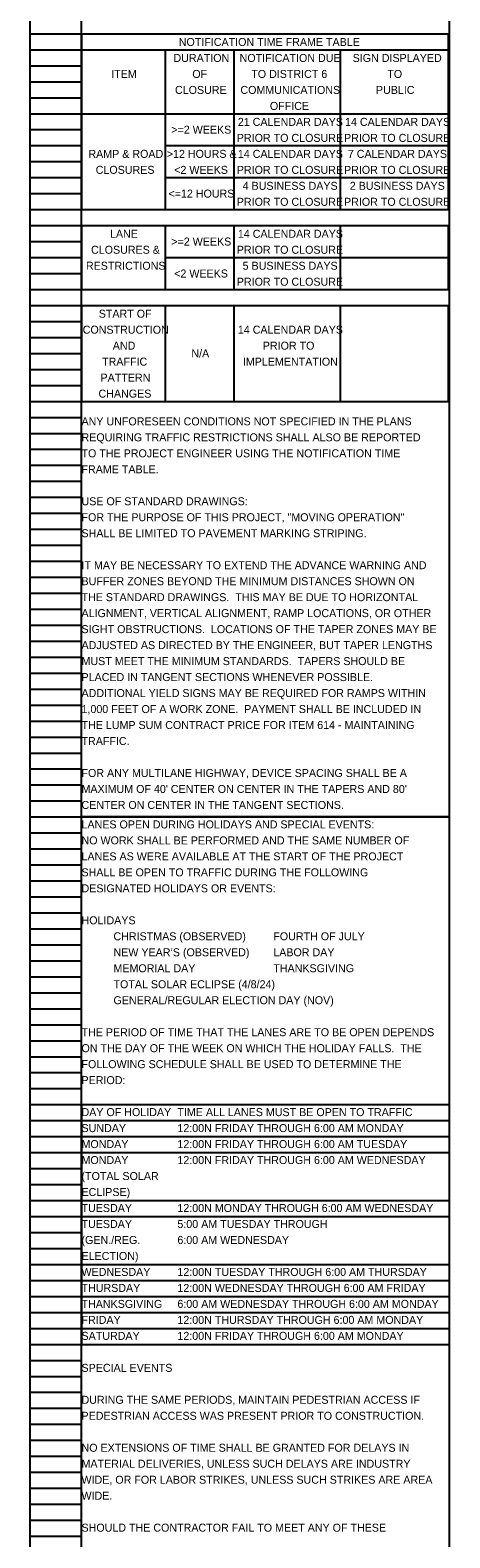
# Model space of a CAD drawing. Extents: x 16463 to 16500, y 5400 to 5823.
# Drawn here: x 16463.05 to 16470.4, y 5770.52 to 5796.94 of the extents above; entities that cross this region are included whole.
import ezdxf

# ---------------------------------------------------------------- set-up
doc = ezdxf.new("R2010")
doc.units = 0
for name, color, linetype in [('Default', 7, 'Continuous'), ('SC_Scratch1', 7, 'Continuous'), ('SH_Data', 7, 'Continuous')]:
    doc.layers.add(name, color=color, linetype=linetype)

msp = doc.modelspace()

# ---------------------------------------------------------------- linework, layer by layer
at = {"layer": 'Default'}
for p, q in [((16463.949, 5778.112), (16470.389, 5778.112)), ((16463.949, 5777.832), (16470.389, 5777.832)), ((16463.949, 5777.552), (16470.389, 5777.552)), ((16463.949, 5777.272), (16470.389, 5777.272)), ((16463.949, 5776.432), (16470.389, 5776.432)), ((16463.949, 5776.152), (16470.389, 5776.152)), ((16463.949, 5775.312), (16470.389, 5775.312)), ((16463.949, 5775.032), (16470.389, 5775.032)), ((16463.949, 5774.752), (16470.389, 5774.752)), ((16463.949, 5774.472), (16470.389, 5774.472)), ((16463.949, 5774.192), (16470.389, 5774.192))]:
    msp.add_line(p, q, dxfattribs=at)
for points in [[(16463.949, 5778.112), (16463.949, 5773.912), (16470.389, 5773.912)], [(16463.949, 5778.112), (16470.389, 5778.112), (16470.389, 5773.912)]]:
    msp.add_lwpolyline(points, dxfattribs=at)
at = {"layer": 'SC_Scratch1'}
for points in [[(16463.949, 5803.312), (16470.389, 5803.312), (16470.389, 5783.152), (16463.949, 5783.152)], [(16463.949, 5783.152), (16470.389, 5783.152), (16470.389, 5762.992), (16463.949, 5762.992)]]:
    msp.add_lwpolyline(points, close=True, dxfattribs=at)
at = {"layer": 'SH_Data'}
for p, q in [((16463.049, 5783.152), (16463.049, 5803.312)), ((16463.949, 5783.152), (16463.949, 5803.312)), ((16463.049, 5796.872), (16463.949, 5796.872)), ((16463.949, 5796.872), (16470.373, 5796.872)), ((16463.949, 5796.872), (16463.949, 5793.792)), ((16470.373, 5796.872), (16470.373, 5793.792)), ((16463.049, 5796.592), (16463.949, 5796.592)), ((16463.949, 5796.592), (16470.373, 5796.592)), ((16465.415, 5796.592), (16465.415, 5793.792)), ((16466.618, 5796.592), (16466.618, 5793.792)), ((16468.479, 5796.592), (16468.479, 5793.792)), ((16463.049, 5796.312), (16463.949, 5796.312)), ((16463.049, 5796.032), (16463.949, 5796.032)), ((16463.049, 5795.752), (16463.949, 5795.752)), ((16463.049, 5795.472), (16463.949, 5795.472)), ((16463.949, 5795.472), (16470.373, 5795.472)), ((16463.049, 5795.192), (16463.949, 5795.192)), ((16463.049, 5794.912), (16463.949, 5794.912)), ((16465.415, 5794.912), (16470.373, 5794.912)), ((16463.049, 5794.632), (16463.949, 5794.632)), ((16463.049, 5794.352), (16463.949, 5794.352)), ((16465.415, 5794.352), (16470.373, 5794.352)), ((16463.049, 5794.072), (16463.949, 5794.072)), ((16463.049, 5793.792), (16463.949, 5793.792)), ((16463.949, 5793.792), (16470.373, 5793.792)), ((16463.049, 5793.512), (16463.949, 5793.512)), ((16463.949, 5793.512), (16470.373, 5793.512)), ((16463.949, 5793.512), (16463.949, 5792.392)), ((16465.415, 5793.512), (16465.415, 5792.392)), ((16466.618, 5793.512), (16466.618, 5792.392)), ((16468.479, 5793.512), (16468.479, 5792.392)), ((16470.373, 5793.512), (16470.373, 5792.392)), ((16463.049, 5793.232), (16463.949, 5793.232)), ((16463.049, 5792.952), (16463.949, 5792.952)), ((16465.415, 5792.952), (16470.373, 5792.952)), ((16463.049, 5792.672), (16463.949, 5792.672)), ((16463.049, 5792.392), (16463.949, 5792.392)), ((16463.949, 5792.392), (16470.373, 5792.392)), ((16463.049, 5792.112), (16463.949, 5792.112)), ((16463.949, 5792.112), (16470.373, 5792.112)), ((16463.949, 5792.112), (16463.949, 5790.432)), ((16465.415, 5792.112), (16465.415, 5790.432)), ((16466.618, 5792.112), (16466.618, 5790.432)), ((16468.479, 5792.112), (16468.479, 5790.432)), ((16470.373, 5792.112), (16470.373, 5790.432)), ((16463.049, 5791.832), (16463.949, 5791.832)), ((16463.049, 5791.552), (16463.949, 5791.552)), ((16463.049, 5791.272), (16463.949, 5791.272)), ((16463.049, 5790.992), (16463.949, 5790.992)), ((16463.049, 5790.712), (16463.949, 5790.712)), ((16463.049, 5790.432), (16463.949, 5790.432)), ((16463.949, 5790.432), (16470.373, 5790.432)), ((16463.049, 5790.152), (16463.949, 5790.152)), ((16463.049, 5789.872), (16463.949, 5789.872)), ((16463.049, 5789.592), (16463.949, 5789.592)), ((16463.049, 5789.312), (16463.949, 5789.312)), ((16463.049, 5789.032), (16463.949, 5789.032)), ((16463.049, 5788.752), (16463.949, 5788.752)), ((16463.049, 5788.472), (16463.949, 5788.472)), ((16463.049, 5788.192), (16463.949, 5788.192)), ((16463.049, 5787.912), (16463.949, 5787.912)), ((16463.049, 5787.632), (16463.949, 5787.632)), ((16463.049, 5787.352), (16463.949, 5787.352)), ((16463.049, 5787.072), (16463.949, 5787.072)), ((16463.049, 5786.792), (16463.949, 5786.792)), ((16463.049, 5786.512), (16463.949, 5786.512)), ((16463.049, 5786.232), (16463.949, 5786.232)), ((16463.049, 5785.952), (16463.949, 5785.952)), ((16463.049, 5785.672), (16463.949, 5785.672)), ((16463.049, 5785.392), (16463.949, 5785.392)), ((16463.049, 5785.112), (16463.949, 5785.112)), ((16463.049, 5784.832), (16463.949, 5784.832)), ((16463.049, 5784.552), (16463.949, 5784.552)), ((16463.049, 5784.272), (16463.949, 5784.272)), ((16463.049, 5783.992), (16463.949, 5783.992)), ((16463.049, 5783.712), (16463.949, 5783.712)), ((16463.049, 5783.432), (16463.949, 5783.432)), ((16463.049, 5762.992), (16463.049, 5783.152)), ((16463.049, 5783.152), (16463.949, 5783.152)), ((16463.049, 5783.152), (16463.949, 5783.152)), ((16463.949, 5762.992), (16463.949, 5783.152)), ((16463.049, 5782.872), (16463.949, 5782.872)), ((16463.049, 5782.592), (16463.949, 5782.592)), ((16463.049, 5782.312), (16463.949, 5782.312)), ((16463.049, 5782.032), (16463.949, 5782.032)), ((16463.049, 5781.752), (16463.949, 5781.752)), ((16463.049, 5781.472), (16463.949, 5781.472)), ((16463.049, 5781.192), (16463.949, 5781.192)), ((16463.049, 5780.912), (16463.949, 5780.912)), ((16463.049, 5780.632), (16463.949, 5780.632)), ((16463.049, 5780.352), (16463.949, 5780.352)), ((16463.049, 5780.072), (16463.949, 5780.072)), ((16463.049, 5779.792), (16463.949, 5779.792)), ((16463.049, 5779.512), (16463.949, 5779.512)), ((16463.049, 5779.232), (16463.949, 5779.232)), ((16463.049, 5778.952), (16463.949, 5778.952)), ((16463.049, 5778.672), (16463.949, 5778.672)), ((16463.049, 5778.392), (16463.949, 5778.392)), ((16463.049, 5778.112), (16463.949, 5778.112)), ((16463.049, 5777.832), (16463.949, 5777.832)), ((16463.049, 5777.552), (16463.949, 5777.552)), ((16463.049, 5777.272), (16463.949, 5777.272)), ((16463.049, 5776.992), (16463.949, 5776.992)), ((16463.049, 5776.712), (16463.949, 5776.712)), ((16463.049, 5776.432), (16463.949, 5776.432)), ((16463.049, 5776.152), (16463.949, 5776.152)), ((16463.049, 5775.872), (16463.949, 5775.872)), ((16463.049, 5775.592), (16463.949, 5775.592)), ((16463.049, 5775.312), (16463.949, 5775.312)), ((16463.049, 5775.032), (16463.949, 5775.032)), ((16463.049, 5774.752), (16463.949, 5774.752)), ((16463.049, 5774.472), (16463.949, 5774.472)), ((16463.049, 5774.192), (16463.949, 5774.192)), ((16463.049, 5773.912), (16463.949, 5773.912)), ((16463.049, 5773.632), (16463.949, 5773.632)), ((16463.049, 5773.352), (16463.949, 5773.352)), ((16463.049, 5773.072), (16463.949, 5773.072)), ((16463.049, 5772.792), (16463.949, 5772.792)), ((16463.049, 5772.512), (16463.949, 5772.512)), ((16463.049, 5772.232), (16463.949, 5772.232)), ((16463.049, 5771.952), (16463.949, 5771.952)), ((16463.049, 5771.672), (16463.949, 5771.672)), ((16463.049, 5771.392), (16463.949, 5771.392)), ((16463.049, 5771.112), (16463.949, 5771.112)), ((16463.049, 5770.832), (16463.949, 5770.832)), ((16463.049, 5770.552), (16463.949, 5770.552))]:
    msp.add_line(p, q, dxfattribs=at)

# ---------------------------------------------------------------- texts
at = {"layer": 'Default'}
for s, p in [('ANY UNFORESEEN CONDITIONS NOT SPECIFIED IN THE PLANS ', (16463.949, 5790.012)), ('REQUIRING TRAFFIC RESTRICTIONS SHALL ALSO BE REPORTED ', (16463.949, 5789.732)), ('TO THE PROJECT ENGINEER USING THE NOTIFICATION TIME ', (16463.949, 5789.452)), ('FRAME TABLE. ', (16463.949, 5789.172)), ('USE OF STANDARD DRAWINGS:', (16463.949, 5788.612)), ('FOR THE PURPOSE OF THIS PROJECT, "MOVING OPERATION" ', (16463.949, 5788.332)), ('SHALL BE LIMITED TO PAVEMENT MARKING STRIPING.', (16463.949, 5788.052)), ('IT MAY BE NECESSARY TO EXTEND THE ADVANCE WARNING AND ', (16463.949, 5787.492)), ('BUFFER ZONES BEYOND THE MINIMUM DISTANCES SHOWN ON ', (16463.949, 5787.212)), ('THE STANDARD DRAWINGS.  THIS MAY BE DUE TO HORIZONTAL ', (16463.949, 5786.932)), ('ALIGNMENT, VERTICAL ALIGNMENT, RAMP LOCATIONS, OR OTHER ', (16463.949, 5786.652)), ('SIGHT OBSTRUCTIONS.  LOCATIONS OF THE TAPER ZONES MAY BE ', (16463.949, 5786.372)), ('ADJUSTED AS DIRECTED BY THE ENGINEER, BUT TAPER LENGTHS ', (16463.949, 5786.092)), ('MUST MEET THE MINIMUM STANDARDS.  TAPERS SHOULD BE ', (16463.949, 5785.812)), ('PLACED IN TANGENT SECTIONS WHENEVER POSSIBLE.  ', (16463.949, 5785.532)), ('ADDITIONAL YIELD SIGNS MAY BE REQUIRED FOR RAMPS WITHIN ', (16463.949, 5785.252)), ('1,000 FEET OF A WORK ZONE.  PAYMENT SHALL BE INCLUDED IN ', (16463.949, 5784.972)), ('THE LUMP SUM CONTRACT PRICE FOR ITEM 614 - MAINTAINING ', (16463.949, 5784.692)), ('TRAFFIC.', (16463.949, 5784.412)), ('FOR ANY MULTILANE HIGHWAY, DEVICE SPACING SHALL BE A ', (16463.949, 5783.852)), ("MAXIMUM OF 40' CENTER ON CENTER IN THE TAPERS AND 80' ", (16463.949, 5783.572)), ('CENTER ON CENTER IN THE TANGENT SECTIONS.', (16463.949, 5783.292)), ('LANES OPEN DURING HOLIDAYS AND SPECIAL EVENTS:', (16463.949, 5782.951)), ('NO WORK SHALL BE PERFORMED AND THE SAME NUMBER OF ', (16463.949, 5782.671)), ('LANES AS WERE AVAILABLE AT THE START OF THE PROJECT ', (16463.949, 5782.391)), ('SHALL BE OPEN TO TRAFFIC DURING THE FOLLOWING ', (16463.949, 5782.111)), ('DESIGNATED HOLIDAYS OR EVENTS:', (16463.949, 5781.831)), ('HOLIDAYS', (16463.949, 5781.271)), ('CHRISTMAS (OBSERVED)', (16464.509, 5780.991)), ('FOURTH OF JULY', (16467.309, 5780.991)), ('NEW YEAR’S (OBSERVED)', (16464.509, 5780.711)), ('LABOR DAY', (16467.309, 5780.711)), ('MEMORIAL DAY          ', (16464.509, 5780.431)), ('THANKSGIVING', (16467.309, 5780.431)), ('TOTAL SOLAR ECLIPSE (4/8/24)', (16464.509, 5780.151)), ('GENERAL/REGULAR ELECTION DAY (NOV)', (16464.509, 5779.871)), ('THE PERIOD OF TIME THAT THE LANES ARE TO BE OPEN DEPENDS ', (16463.949, 5779.311)), ('ON THE DAY OF THE WEEK ON WHICH THE HOLIDAY FALLS.  THE ', (16463.949, 5779.031)), ('FOLLOWING SCHEDULE SHALL BE USED TO DETERMINE THE ', (16463.949, 5778.751)), ('PERIOD:', (16463.949, 5778.471)), ('DAY OF HOLIDAY', (16463.949, 5777.911)), ('TIME ALL LANES MUST BE OPEN TO TRAFFIC', (16465.629, 5777.911)), ('SUNDAY', (16463.949, 5777.631)), ('12:00N FRIDAY THROUGH 6:00 AM MONDAY', (16465.629, 5777.631)), ('MONDAY', (16463.949, 5777.351)), ('12:00N FRIDAY THROUGH 6:00 AM TUESDAY', (16465.629, 5777.351)), ('MONDAY', (16463.949, 5777.071)), ('12:00N FRIDAY THROUGH 6:00 AM WEDNESDAY', (16465.629, 5777.071)), ('(TOTAL SOLAR ', (16463.949, 5776.791)), ('ECLIPSE)', (16463.949, 5776.511)), ('TUESDAY', (16463.949, 5776.231)), ('12:00N MONDAY THROUGH 6:00 AM WEDNESDAY', (16465.629, 5776.231)), ('TUESDAY', (16463.949, 5775.951)), ('5:00 AM TUESDAY THROUGH  ', (16465.629, 5775.951)), ('(GEN./REG.', (16463.949, 5775.671)), ('6:00 AM WEDNESDAY', (16465.629, 5775.671)), ('ELECTION)', (16463.949, 5775.391)), ('WEDNESDAY', (16463.949, 5775.111)), ('12:00N TUESDAY THROUGH 6:00 AM THURSDAY', (16465.629, 5775.111)), ('THURSDAY', (16463.949, 5774.831)), ('12:00N WEDNESDAY THROUGH 6:00 AM FRIDAY', (16465.629, 5774.831)), ('THANKSGIVING', (16463.949, 5774.551)), ('6:00 AM WEDNESDAY THROUGH 6:00 AM MONDAY', (16465.629, 5774.551)), ('FRIDAY', (16463.949, 5774.271)), ('12:00N THURSDAY THROUGH 6:00 AM MONDAY', (16465.629, 5774.271)), ('SATURDAY', (16463.949, 5773.991)), ('12:00N FRIDAY THROUGH 6:00 AM MONDAY', (16465.629, 5773.991)), ('SPECIAL EVENTS', (16463.949, 5773.431)), ('DURING THE SAME PERIODS, MAINTAIN PEDESTRIAN ACCESS IF ', (16463.949, 5772.871)), ('PEDESTRIAN ACCESS WAS PRESENT PRIOR TO CONSTRUCTION.', (16463.949, 5772.591)), ('NO EXTENSIONS OF TIME SHALL BE GRANTED FOR DELAYS IN ', (16463.949, 5772.031)), ('MATERIAL DELIVERIES, UNLESS SUCH DELAYS ARE INDUSTRY ', (16463.949, 5771.751)), ('WIDE, OR FOR LABOR STRIKES, UNLESS SUCH STRIKES ARE AREA ', (16463.949, 5771.471)), ('WIDE.', (16463.949, 5771.191)), ('SHOULD THE CONTRACTOR FAIL TO MEET ANY OF THESE ', (16463.949, 5770.631))]:
    msp.add_text(s, height=0.14, dxfattribs=at).set_placement(p)
at = {"layer": 'SH_Data'}
for s, p in [('NOTIFICATION TIME FRAME TABLE', (16465.653, 5796.658)), ('DURATION', (16465.56, 5796.378)), ('NOTIFICATION DUE', (16466.719, 5796.378)), ('SIGN DISPLAYED', (16468.699, 5796.378)), ('ITEM', (16464.469, 5796.098)), ('OF', (16465.89, 5796.098)), ('TO DISTRICT 6', (16466.923, 5796.098)), ('TO', (16469.306, 5796.098)), ('CLOSURE', (16465.587, 5795.818)), ('COMMUNICATIONS', (16466.733, 5795.818)), ('PUBLIC', (16469.107, 5795.818)), (' OFFICE', (16467.197, 5795.538)), ('21 CALENDAR DAYS', (16466.688, 5795.258)), ('14 CALENDAR DAYS', (16468.566, 5795.258)), ('>=2 WEEKS', (16465.522, 5795.122)), ('PRIOR TO CLOSURE', (16466.67, 5794.978)), ('PRIOR TO CLOSURE', (16468.548, 5794.978)), ('RAMP & ROAD', (16464.07, 5794.698)), ('>12 HOURS &', (16465.443, 5794.698)), ('14 CALENDAR DAYS', (16466.688, 5794.698)), ('7 CALENDAR DAYS', (16468.615, 5794.698)), ('CLOSURES', (16464.198, 5794.418)), ('<2 WEEKS', (16465.573, 5794.418)), ('PRIOR TO CLOSURE', (16466.67, 5794.418)), ('PRIOR TO CLOSURE', (16468.548, 5794.418)), ('<=12 HOURS', (16465.473, 5794.002)), ('4 BUSINESS DAYS', (16466.772, 5794.138)), ('2 BUSINESS DAYS', (16468.649, 5794.138)), ('PRIOR TO CLOSURE', (16466.67, 5793.858)), ('PRIOR TO CLOSURE', (16468.548, 5793.858)), ('LANE', (16464.448, 5793.298)), ('>=2 WEEKS', (16465.522, 5793.162)), ('14 CALENDAR DAYS', (16466.688, 5793.298)), ('CLOSURES &', (16464.116, 5793.018)), ('PRIOR TO CLOSURE', (16466.67, 5793.018)), ('RESTRICTIONS', (16464.027, 5792.738)), ('5 BUSINESS DAYS', (16466.772, 5792.738)), ('<2 WEEKS', (16465.573, 5792.602)), ('PRIOR TO CLOSURE', (16466.67, 5792.458)), ('START OF', (16464.251, 5791.898)), ('CONSTRUCTION', (16463.97, 5791.618)), ('14 CALENDAR DAYS', (16466.688, 5791.618)), ('AND', (16464.497, 5791.338)), ('PRIOR TO', (16467.125, 5791.338)), ('TRAFFIC', (16464.31, 5791.058)), ('N/A', (16465.874, 5791.202)), ('IMPLEMENTATION', (16466.776, 5791.058)), ('PATTERN', (16464.282, 5790.778)), ('CHANGES', (16464.247, 5790.498))]:
    msp.add_text(s, height=0.14, dxfattribs=at).set_placement(p)

doc.saveas('drawing.dxf')
